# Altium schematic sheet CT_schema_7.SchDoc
size 287 x 160 mm
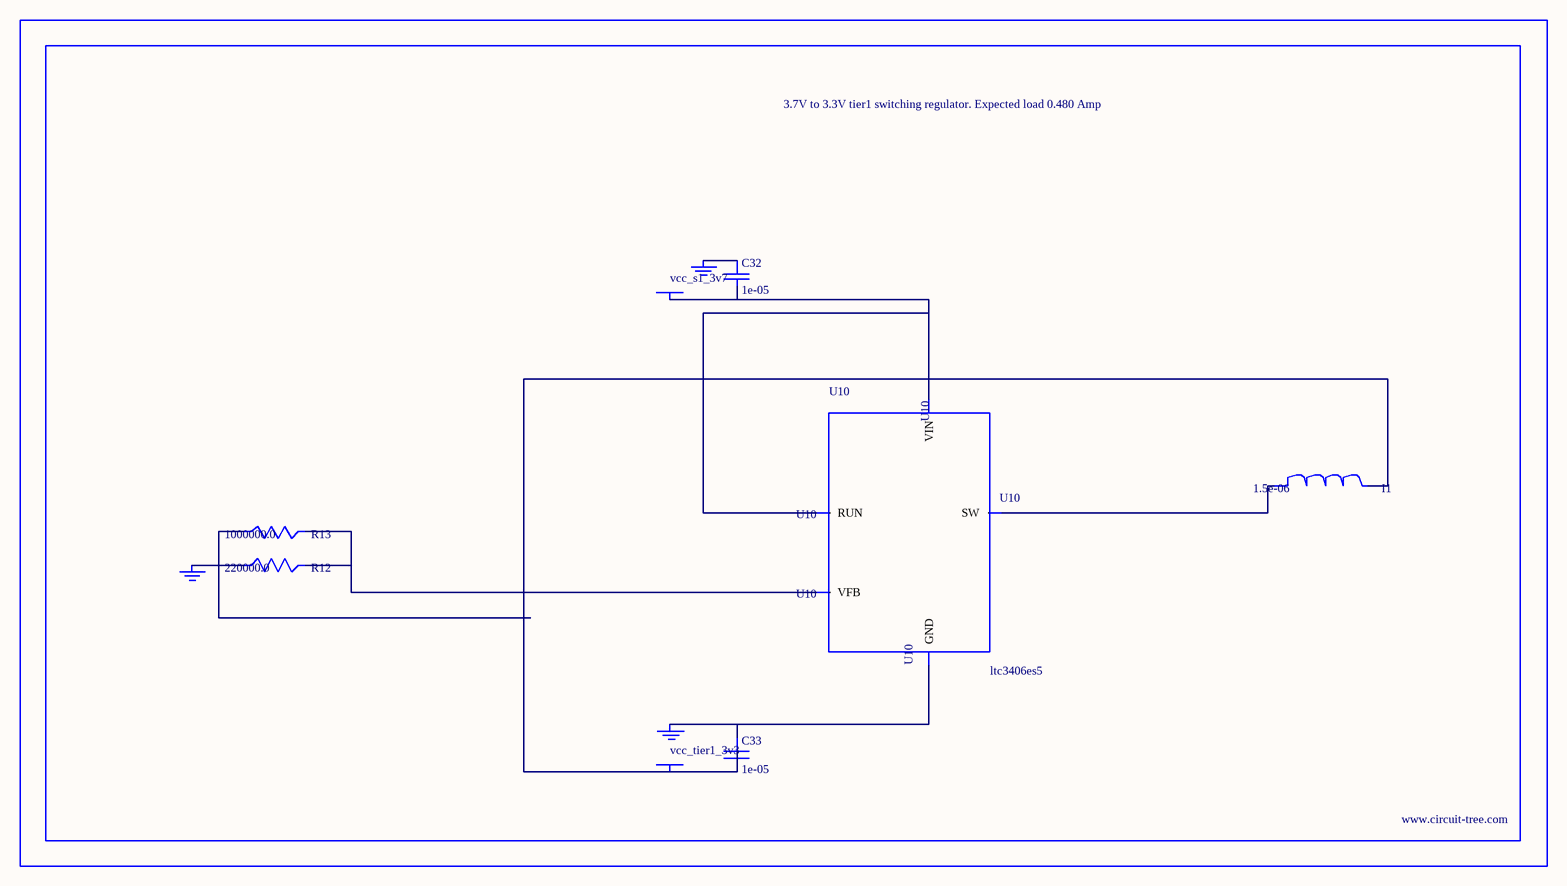
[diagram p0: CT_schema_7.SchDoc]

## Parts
BORDER6  (no value)
C32  1e-05  [C0805]
C33  1e-05  [C0805]
GND_INSTANCE_6_0  (no value)
GND_INSTANCE_6_1  (no value)
GND_INSTANCE_6_2  (no value)
I1  1.5e-06  [L0806]
POWER_INSTANCE_6_0  vcc_tier1_3v3
POWER_INSTANCE_6_1  vcc_s1_3v7
R12  220000.0  [R0603]
R13  1000000.0  [R0603]
U10  ltc3406es5  [TSOT-23-5]

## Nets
NetC32_1: C32.1 GND_INSTANCE_6_1.0(GND)
NetC32_2: C32.2 POWER_INSTANCE_6_1.0(PWR) U10.1(RUN) U10.4(VIN)
NetC33_1: C33.1 GND_INSTANCE_6_0.0(GND) U10.2(GND)
NetC33_2: C33.2 I1.2 POWER_INSTANCE_6_0.0(PWR) R13.1
NetGND_INSTANCE_6_2_0: GND_INSTANCE_6_2.0(GND) R12.1
NetI1_1: I1.1 U10.3(SW)
NetR12_2: R12.2 R13.2 U10.5(VFB)

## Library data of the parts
BORDER6 = BORDER_PAGE6
C32 C33 = C0805C106K8RACTU
GND_INSTANCE_6_0-GND_INSTANCE_6_2 = GND
I1 = L0806C1R5MDWIT
POWER_INSTANCE_6_0 POWER_INSTANCE_6_1 = PWR
R12 = RC0603JR-07220KL
R13 = RC0603JR-071ML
